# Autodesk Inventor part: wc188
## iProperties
Shininess: 64.0
Length Units: 11272
Angle Units: 11279
Time Units: 11290
Mass Units: 11286
Length Display Precision: 3
Angle Display Precision: 2
Compacted: True
Part Number: wc188
Document SubType Name: Modeling
Created: 2004-08
Designer: John Blackburn
Manufacturer: Standard
Standards Organization: Custom
Density: 0.0
Volumn: 0.0
Area: 0.0
PropertySet Name: Model Information
Control State: 0
Master: False
Checked Out: False
Author: John Blackburn
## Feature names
1. Base1
